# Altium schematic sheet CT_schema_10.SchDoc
size 274 x 160 mm
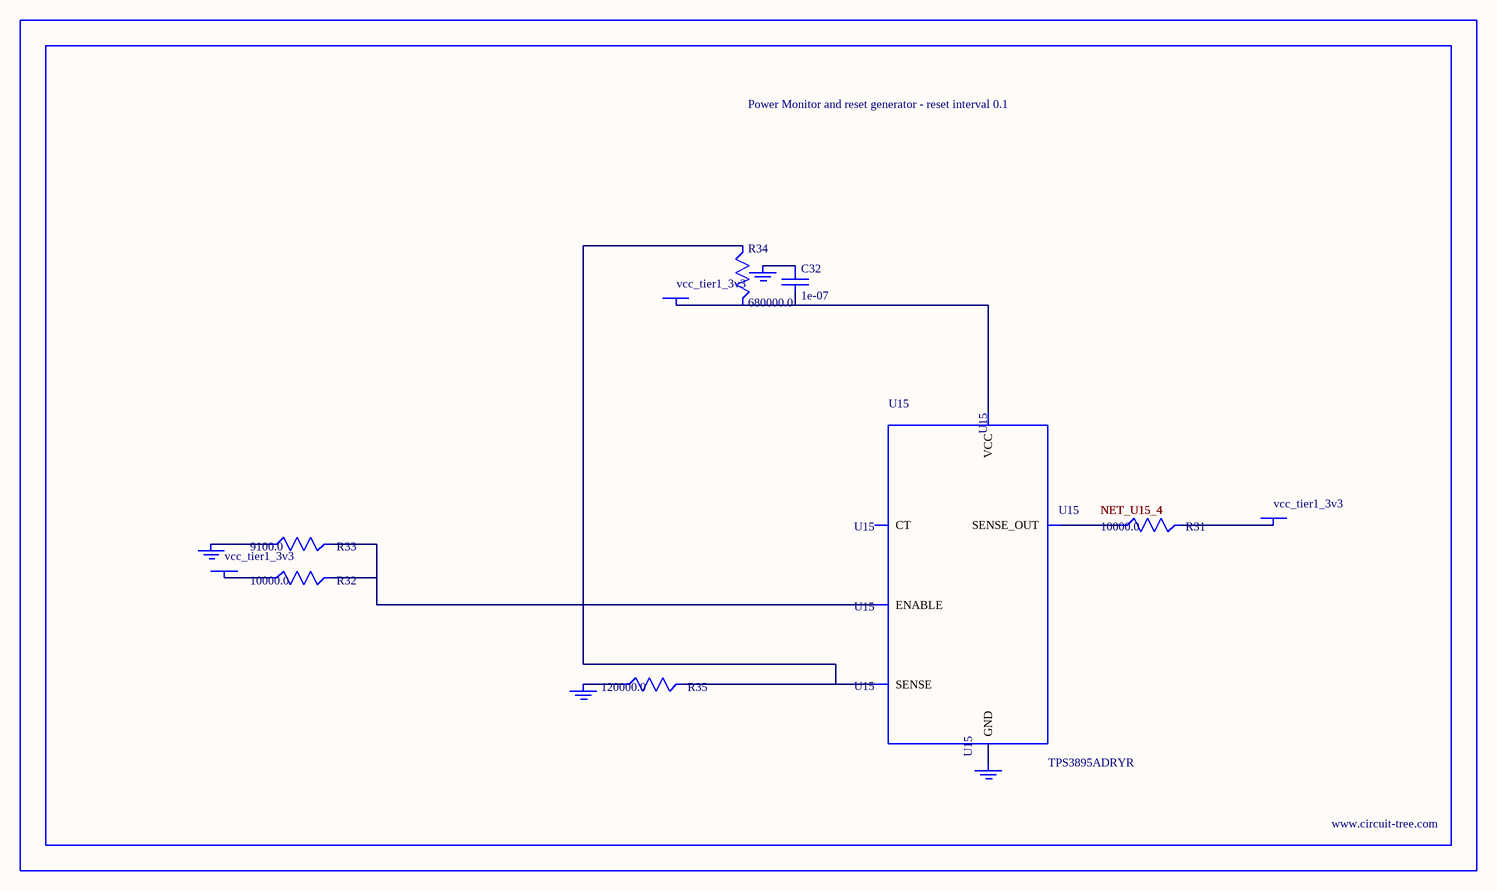
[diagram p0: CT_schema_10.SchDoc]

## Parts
BORDER9  (no value)
C32  1e-07  [C0402]
GND_INSTANCE_9_0  (no value)
GND_INSTANCE_9_1  (no value)
GND_INSTANCE_9_2  (no value)
GND_INSTANCE_9_3  (no value)
POWER_INSTANCE_9_0  vcc_tier1_3v3
POWER_INSTANCE_9_1  vcc_tier1_3v3
POWER_INSTANCE_9_2  vcc_tier1_3v3
R31  10000.0  [R0603]
R32  10000.0  [R0603]
R33  9100.0  [R0603]
R34  680000.0  [R0603]
R35  120000.0  [R0603]
U15  TPS3895ADRYR  [SON-6]

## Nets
NetC32_1: C32.1 GND_INSTANCE_9_2.0(GND)
NetC32_2: C32.2 POWER_INSTANCE_9_2.0(PWR) R34.2 U15.6(VCC)
NetGND_INSTANCE_9_0_0: GND_INSTANCE_9_0.0(GND) R33.1
NetGND_INSTANCE_9_1_0: GND_INSTANCE_9_1.0(GND) R35.1
NetGND_INSTANCE_9_3_0: GND_INSTANCE_9_3.0(GND) U15.2(GND)
NetPOWER_INSTANCE_9_0_0: POWER_INSTANCE_9_0.0(PWR) R32.1
NetPOWER_INSTANCE_9_1_0: POWER_INSTANCE_9_1.0(PWR) R31.2
NetR31_1: R31.1 U15.4(SENSE_OUT)
NetR32_2: R32.2 R33.2 U15.1(ENABLE)
NetR34_1: R34.1 R35.2 U15.3(SENSE)

Not connected (* = marked no-connect by the designer): U15 5(CT)

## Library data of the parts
BORDER9 = BORDER_PAGE9
C32 = C0402C104K3RACTU
GND_INSTANCE_9_0-GND_INSTANCE_9_3 = GND
POWER_INSTANCE_9_0-POWER_INSTANCE_9_2 = PWR
R31 R32 = RC0603JR-0710KL
R33 = RC0603JR-079K1L
R34 = RC0603JR-07680KL
R35 = RC0603JR-07120KL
